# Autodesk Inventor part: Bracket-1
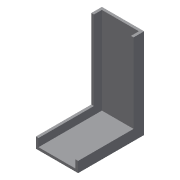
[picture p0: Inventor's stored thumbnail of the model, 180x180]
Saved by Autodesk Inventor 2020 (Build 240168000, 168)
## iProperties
Created: 2002-04
Part Number: Bracket-1
Document SubType Name: Modeling
Density: 1 g/cm^3
Material: Generic
Appearance: Default
Control State: 0
Master: False
Checked Out: False
Shininess: 77.0
Length Units: 11269
Angle Units: 11279
Time Units: 11290
Mass Units: 11283
Length Display Precision: 3
Angle Display Precision: 2
Density: 0.0
Volumn: 0.0
Area: 0.0
PropertySet Name: Model Information
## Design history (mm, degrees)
node "Sketch1"
sketch "Sketch2"
  geometry: L1 (-4.258, 23.699)-(-4.258, -18.801); L2 (-4.258, -18.801)-(26.992, -18.801); L3 (26.992, -18.801)-(26.992, -13.801); L4 (26.992, -13.801)-(0.742, -13.801); L5 (0.742, -13.801)-(0.742, 23.699); L6 (0.742, 23.699)-(-4.258, 23.699)
  constraints: 12 end point, 4 parallel, 2 perpendicular, 1 vertical
  dimensions: "d0" = 31.25 distance of L1.end L2.end; "d1" = 42.5 distance of L1.start L1.end; "d2" = 5 distance of L2.end L3.end
extrude "Extrusion1" new body sketch "Sketch2" stored distance "d3" = 20; taper "d4" = 0 deg
shell "Shell1" dims "d5" = 1.25
body "Solid1"
